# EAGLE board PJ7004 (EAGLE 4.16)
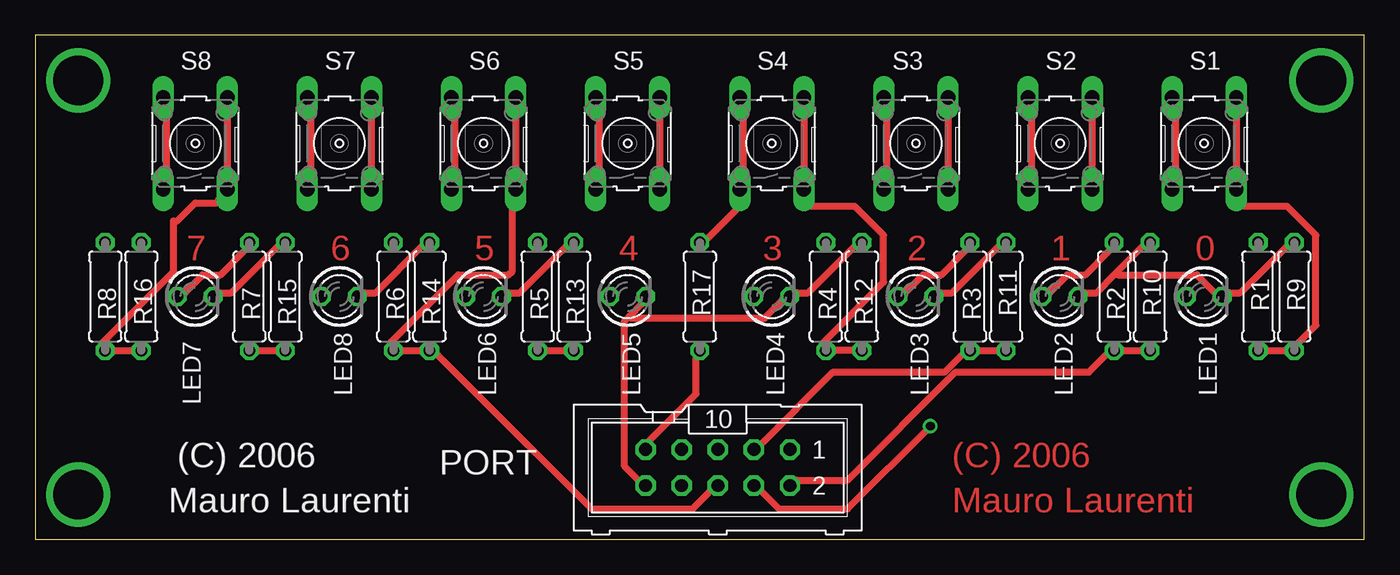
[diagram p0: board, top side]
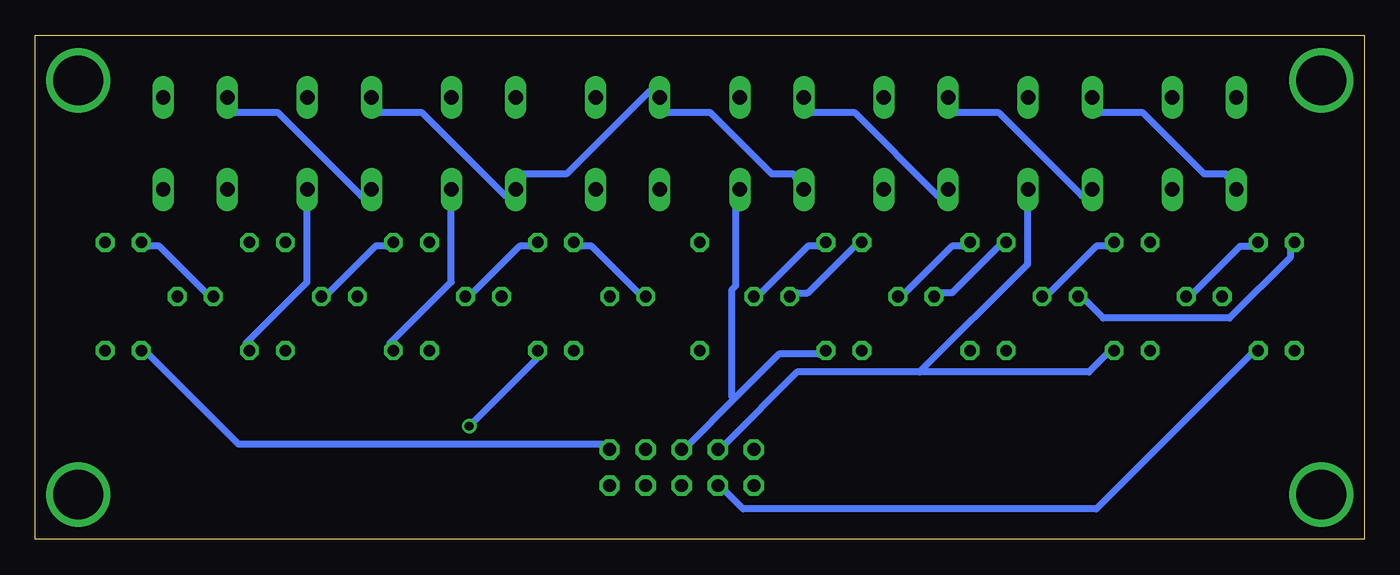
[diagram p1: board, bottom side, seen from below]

Size 93.65 x 35.55 mm. Coordinates in mm from the lower left corner, seen from the top.
Outline: 0,0 93.65,0 93.65,35.55 0,35.55 0,0
Copper layers (1*16): Top 0.035mm / dielectric 1.5mm / Bottom 0.035mm
Design rules "MonofacciaEagle": minimum track width 0.5mm, minimum drill 24mil, track to track 0.0038mm, track to pad 0.5mm, pad to pad 0.5mm, via to via 0.5mm, smd to smd 0.5mm, copper to edge 40mil, drill to drill 8mil, minimum pad ring 10mil, minimum via ring 8mil, stop-mask expansion 4mil, vias tented up to drill 0mil, thermal gap 10mil

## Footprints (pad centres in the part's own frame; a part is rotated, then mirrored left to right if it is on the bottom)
LED3MM = drill 0.813 octagon: A -1.27,0; K 1.27,0
ML10 = drill 0.914 octagon: 1 -5.08,-1.27; 2 -5.08,1.27; 3 -2.54,-1.27; 4 -2.54,1.27; 5 0,-1.27; 6 0,1.27; 7 2.54,-1.27; 8 2.54,1.27; 9 5.08,-1.27; 10 5.08,1.27
0207/7 = drill 0.813 octagon: 1 -3.81,0; 2 3.81,0
B3F-10XX = drill 1.016 long: 1 -3.251,2.261; 2 3.251,2.261; 3 -3.251,-2.261; 4 3.251,-2.261

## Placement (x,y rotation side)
LED1  [LED3MM]  82.39,17.14 0 top
LED2  [LED3MM]  72.23,17.14 0 top
LED3  [LED3MM]  62.06,17.14 0 top
LED4  [LED3MM]  51.91,17.14 0 top
LED5  [LED3MM]  41.75,17.14 0 top
LED6  [LED3MM]  31.59,17.14 0 top
LED7  [LED3MM]  11.27,17.14 0 top
LED8  [LED3MM]  21.42,17.14 0 top
PORT  [ML10]  48.09,5.08 180 top
R1  220  [0207/7]  86.2,17.14 270 top
R2  220  [0207/7]  76.03,17.14 270 top
R3  220  [0207/7]  65.88,17.14 270 top
R4  220  [0207/7]  55.72,17.14 270 top
R5  220  [0207/7]  35.4,17.14 270 top
R6  220  [0207/7]  25.23,17.14 270 top
R7  220  [0207/7]  15.08,17.14 270 top
R8  220  [0207/7]  4.92,17.14 270 top
R9  10K  [0207/7]  88.73,17.14 270 top
R10  10K  [0207/7]  78.58,17.14 270 top
R11  10K  [0207/7]  68.42,17.14 270 top
R12  10K  [0207/7]  58.26,17.14 270 top
R13  10K  [0207/7]  37.94,17.14 270 top
R14  10K  [0207/7]  27.77,17.14 270 top
R15  10K  [0207/7]  17.62,17.14 270 top
R16  10K  [0207/7]  7.46,17.14 270 top
R17  220  [0207/7]  46.83,17.14 270 top
S1  [B3F-10XX]  82.39,27.94 90 top
S2  [B3F-10XX]  72.23,27.94 90 top
S3  [B3F-10XX]  62.06,27.94 90 top
S4  [B3F-10XX]  51.91,27.94 90 top
S5  [B3F-10XX]  41.75,27.94 90 top
S6  [B3F-10XX]  31.59,27.94 90 top
S7  [B3F-10XX]  21.42,27.94 90 top
S8  [B3F-10XX]  11.27,27.94 90 top

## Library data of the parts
LED1-LED8 = led
PORT = con-harting-ml
R1-R17 = rcl
S1-S8 = switch-omron

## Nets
GND: LED1.K LED2.K LED3.K LED4.K LED5.K LED6.K LED7.K LED8.K PORT.10 R9.1 R10.1 R11.1 R12.1 R13.1 R14.1 R15.1 R16.1
N$1: PORT.1 R1.2 R9.2 S1.3 S1.4
N$2: PORT.2 R2.2 R10.2 S2.3 S2.4
N$3: PORT.3 R3.2 R11.2 S3.3 S3.4
N$4: PORT.4 R4.2 R12.2 S4.3 S4.4
N$5: PORT.5 R5.2 R13.2 S5.3 S5.4
N$6: PORT.6 R6.2 R14.2 S6.3 S6.4
N$7: PORT.7 R7.2 R15.2 S7.3 S7.4
N$8: PORT.8 R8.2 R16.2 S8.3 S8.4
N$9: LED1.A R1.1
N$10: LED2.A R2.1
N$11: LED3.A R3.1
N$12: LED4.A R4.1
N$13: LED5.A R5.1
N$14: LED6.A R6.1
N$15: LED7.A R7.1
N$16: LED8.A R8.1
N$21: R17.1 S1.1 S1.2 S2.1 S2.2 S3.1 S3.2 S4.1 S4.2 S5.1 S5.2 S6.1 S6.2 S7.1 S7.2 S8.1 S8.2
VCC: PORT.9 R17.2

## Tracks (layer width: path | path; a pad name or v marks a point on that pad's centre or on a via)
GND
  Top 0.5: R9.1 88.23,20.7 84.92,17.39 84.16,17.39 LED1.K 83.15,17.39 81.88,18.66 76.29,18.66 76.16,18.79 | 76.16,18.79 78.07,20.7 R10.1 | 76.16,18.79 74.77,17.39 74,17.39 LED2.K | R12.1 57.75,20.7 54.45,17.39 53.68,17.39 LED4.K 52.67,16.89 51.4,15.62 42,15.62 41.87,15.74 | LED3.K 63.84,17.39 64.61,17.39 67.91,20.7 R11.1 | LED7.K 13.04,17.39 13.81,17.39 17.11,20.7 R15.1 | LED8.K 23.2,17.39 23.97,17.39 27.27,20.7 R14.1 | LED6.K 33.36,17.39 34.12,17.39 37.43,20.7 R13.1 | 41.87,15.74 42.76,16.63 LED5.K | 41.87,15.74 41.49,15.36 41.49,5.2 42.51,4.19 PORT.10
  Bottom 0.5: R12.1 58.76,20.7 59.52,20.7 62.83,17.39 LED3.K | LED2.K 72.99,17.39 69.69,20.7 68.92,20.7 R11.1 | R16.1 7.96,20.7 8.72,20.7 12.03,17.39 LED7.K | LED5.K 42.51,17.39 39.2,20.7 38.44,20.7 R13.1 | R14.1 28.28,20.7 29.05,20.7 32.35,17.39 LED6.K | R15.1 18.12,20.7 18.88,20.7 22.19,17.39 LED8.K
N$1
  Top 0.5: S1.4 84.67,29.84 84.67,26.03 S1.3 85.18,23.49 88.23,23.49 90.26,21.46 90.26,15.11 88.99,13.84 R9.2 R1.2
  Bottom 0.5: PORT.1 53.68,6.73 79.34,6.73 85.69,13.08 R1.2
N$2
  Top 0.5: S2.3 74.51,26.03 74.51,29.84 S2.4 | R10.2 R2.2 75.53,13.08 74.26,11.81 64.86,11.81 57.24,4.19 53.68,4.19 PORT.2
  Bottom 0.5: S2.3 74.51,23.24 74.51,18.16 78.83,13.84 R10.2
N$3
  Top 0.5: S3.3 64.35,26.03 64.35,29.84 S3.4 | R11.2 R3.2 65.37,13.08 64.1,11.81 56.22,11.81 51.14,6.73 PORT.3
  Bottom 0.5: S3.3 64.35,23.24 64.35,18.16 68.67,13.84 R11.2
N$4  (via drill 0.61)
  Top 0.5: S4.4 54.19,29.84 54.19,26.03 S4.3 54.7,23.49 57.75,23.49 59.78,21.46 59.78,18.16 55.46,13.84 R4.2 R12.2 | v63.08,8 57.24,2.15 52.41,2.15 51.14,3.42 PORT.4
  Bottom 0.5: v63.08,8 58.26,12.82 R12.2
N$5
  Top 0.5: S5.3 44.03,26.03 44.03,29.84 S5.4 | R5.2 R13.2
  Bottom 0.5: 44.41,9.9 41.24,13.08 38.44,13.08 R13.2 | 44.41,9.9 47.59,6.73 PORT.5 | S5.3 44.29,23.24 44.29,17.9 44.54,17.65 44.54,10.03 44.41,9.9
N$6
  Top 0.5: S6.4 33.87,29.84 33.87,26.03 S6.3 33.62,23.24 33.62,18.92 33.36,18.66 29.81,18.66 24.98,13.84 R6.2 R14.2 28.28,13.08 39.2,2.15 46.32,2.15 47.59,3.42 PORT.6
N$7
  Top 0.5: S7.3 23.71,26.03 23.71,29.84 S7.4 | R7.2 R15.2
  Bottom 0.5: 31.33,11.81 19.39,11.81 18.12,13.08 R15.2 | 31.33,11.81 39.97,11.81 45.05,6.73 PORT.7 | 31.33,11.81 23.71,19.43 23.71,23.24 S7.3
N$8
  Top 0.5: S8.4 13.55,29.84 13.55,26.03 S8.3 12.79,23.74 11.27,23.74 9.99,22.47 9.74,22.47 9.74,18.92 4.66,13.84 R8.2 R16.2
  Bottom 0.5: PORT.8 45.05,3.42 43.78,2.15 18.88,2.15 7.96,13.08 R16.2
N$9
  Bottom 0.5: LED1.A 81.62,17.39 84.92,20.7 85.69,20.7 R1.1
N$10
  Top 0.5: LED2.A 71.46,17.39 72.73,18.66 74,18.66 75.78,20.44 R2.1
N$11
  Top 0.5: LED3.A 61.3,17.39 62.57,18.66 63.84,18.66 65.62,20.44 R3.1
N$12
  Bottom 0.5: LED4.A 51.14,17.39 54.45,20.7 55.21,20.7 R4.1
N$13
  Bottom 0.5: R5.1 35.9,20.7 39.2,17.39 39.97,17.39 LED5.A
N$14
  Bottom 0.5: LED6.A 29.81,17.39 29.05,17.39 25.74,20.7 R6.1
N$15
  Top 0.5: LED7.A 10.5,17.39 11.77,18.66 13.04,18.66 14.82,20.44 R7.1
N$16
  Bottom 0.5: R8.1 5.17,20.44 5.17,19.93 9.49,15.62 18.38,15.62 19.65,16.89 LED8.A
N$17  (via drill 3.5)
  other vias: 3.01,32.38
N$18  (via drill 3.5)
  other vias: 90.64,32.38
N$19  (via drill 3.5)
  other vias: 90.64,3.17
N$20  (via drill 3.5)
  other vias: 3.01,3.17
N$21
  Top 0.5: S5.1 39.71,26.03 39.71,29.84 S5.2 | S6.1 29.55,26.03 29.55,29.84 S6.2 | S8.1 9.23,26.03 9.23,29.84 S8.2 | S7.1 19.39,26.03 19.39,29.84 S7.2 | S1.1 80.35,26.03 80.35,29.84 S1.2 | S2.1 70.19,26.03 70.19,29.84 S2.2 | S3.1 60.03,26.03 60.03,29.84 S3.2 | S4.2 49.87,29.84 49.87,26.03 S4.1 49.37,23.24 47.33,21.2 R17.1
  Bottom 0.5: S8.1 9.74,25.78 11.27,25.78 15.58,30.09 18.63,30.09 S7.2 | S6.2 28.79,30.09 25.74,30.09 19.9,24.25 S7.1 | S5.2 38.95,30.09 35.9,30.09 30.06,24.25 S6.1 | S2.2 69.43,30.09 66.38,30.09 60.54,24.25 S3.1 59.27,25.78 56.22,25.78 50.38,31.62 S4.2 49.11,30.09 46.06,30.09 41.75,25.78 40.22,25.78 S5.1 | S1.2 79.59,30.09 76.54,30.09 70.7,24.25 S2.1
VCC
  Top 0.5: R17.2 46.57,12.82 46.57,10.28 43.27,6.98 PORT.9

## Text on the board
Top: 7 | 6 | 5 | 4 | 3 | 2 | 1 | 0 | (C) 2006 | Mauro Laurenti
tPlace: (C) 2006 | Mauro Laurenti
